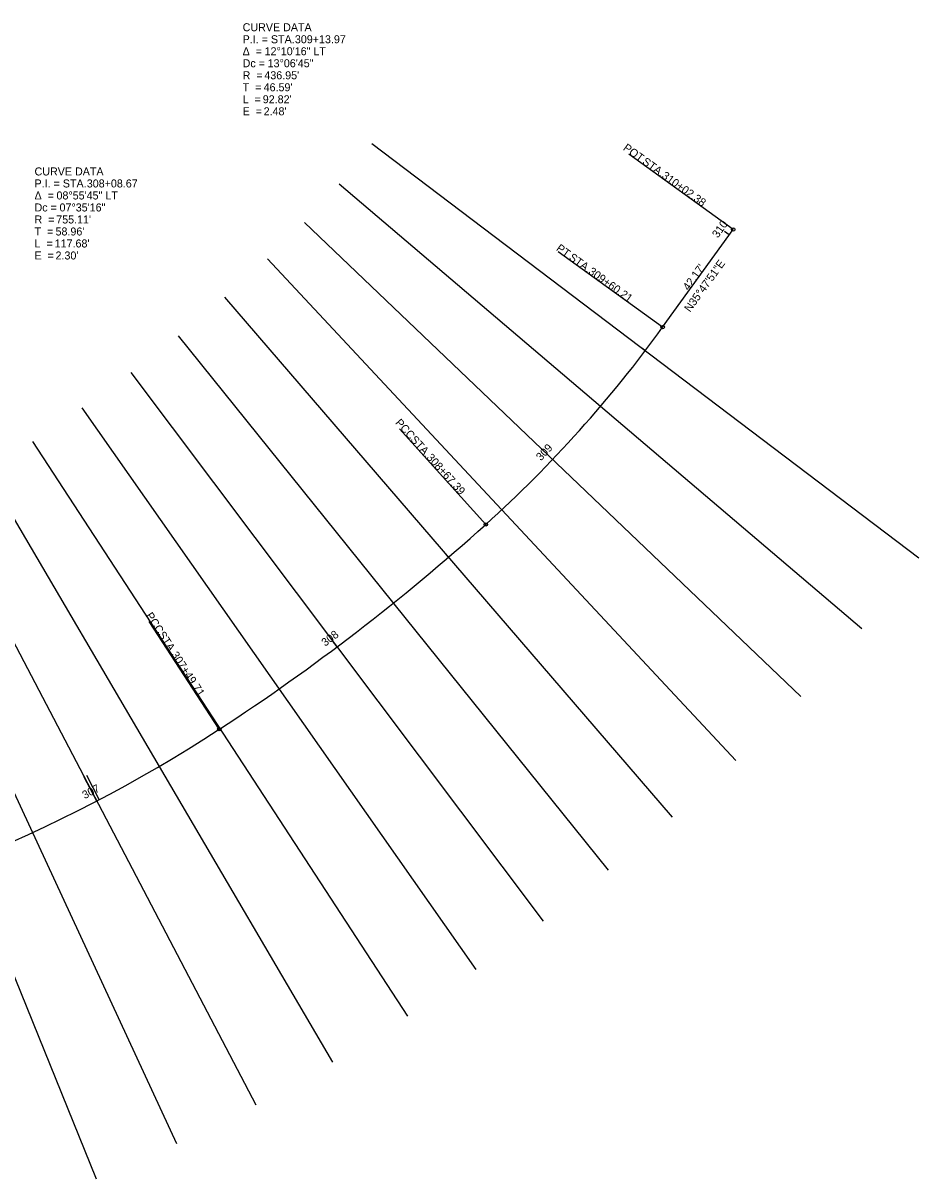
# Model space of a CAD drawing. Extents: x 153902 to 157473, y 413085 to 414252.
# Drawn here: x 154466.5 to 154779.8, y 413626.5 to 414030.9 of the extents above; entities that cross this region are included whole.
import ezdxf

# ---------------------------------------------------------------- set-up
doc = ezdxf.new("R2010")
doc.units = 0
for name, color, linetype in [('GE_P_Alignment', 7, 'Continuous'), ('GE_P_Alignment_100_Bearings', 7, 'Continuous'), ('GE_P_Alignment_100_Cardinal_Points', 7, 'Continuous'), ('GE_P_Alignment_100_Distances', 7, 'Continuous'), ('GE_P_Alignment_100_Stations', 7, 'Continuous'), ('PF_X_Ground_Line', 7, 'Continuous'), ('PM_X_Cells', 7, 'Continuous'), ('PV_X_Text', 7, 'Continuous')]:
    doc.layers.add(name, color=color, linetype=linetype)

msp = doc.modelspace()

# ---------------------------------------------------------------- linework, layer by layer
at = {"layer": 'GE_P_Alignment'}
msp.add_line((154690.16, 413924.47), (154714.83, 413958.67), dxfattribs=at)
for centre, radius, start, end in [((154335.75, 414180.05), 436.95, 312.0315, 324.2025), ((154122.74, 414416.37), 755.11, 303.10232, 312.03145), ((154251.74, 414218.49), 518.89, 280.6558, 303.1023)]:
    msp.add_arc(centre, radius, start, end, dxfattribs=at)
at = {"layer": 'GE_P_Alignment_100_Cardinal_Points'}
for p, q in [((154714.83, 413958.67), (154678.33, 413984.99)), ((154690.16, 413924.47), (154653.66, 413950.79)), ((154628.31, 413855.49), (154598.18, 413888.92)), ((154535.13, 413783.82), (154510.55, 413821.51))]:
    msp.add_line(p, q, dxfattribs=at)
for centre in [(154714.83, 413958.67), (154690.16, 413924.47), (154628.31, 413855.49), (154535.13, 413783.82)]:
    msp.add_circle(centre, 0.6, dxfattribs=at)
at = {"layer": 'PF_X_Ground_Line'}
for p, q in [((154713.43, 413956.74), (154711.81, 413957.91)), ((154684.09, 413916.26), (154683.14, 413916.98)), ((154651.69, 413878.21), (154650.25, 413879.59)), ((154615.26, 413844), (154614.48, 413844.91)), ((154576.31, 413812.67), (154575.11, 413814.27)), ((154535.37, 413783.98), (154534.71, 413784.98)), ((154492.25, 413758.71), (154491.32, 413760.48))]:
    msp.add_line(p, q, dxfattribs=at)
at = {"layer": 'PM_X_Cells'}
for p, q in [((154492.25, 413758.71), (154487.77, 413767.27)), ((154488.65, 413767.74), (154493.13, 413759.17))]:
    msp.add_line(p, q, dxfattribs=at)
at = {"layer": 'PV_X_Text'}
for p, q in [((154588.43, 413988.7), (154779.76, 413843.82)), ((154759.8, 413818.98), (154577.07, 413974.57)), ((154564.93, 413961.11), (154738.46, 413795.32)), ((154715.8, 413772.92), (154552.03, 413948.36)), ((154536.99, 413934.96), (154693.53, 413753.04)), ((154671.26, 413734.51), (154520.83, 413921.51)), ((154504.23, 413908.61), (154648.39, 413716.73)), ((154624.94, 413699.71), (154487.21, 413896.26)), ((154469.79, 413884.48), (154600.94, 413683.48)), ((154574.79, 413667.29), (154453.44, 413874.35)), ((154436.63, 413865.04), (154547.87, 413652.37)), ((154520.26, 413638.77), (154419.39, 413856.54)), ((154401.76, 413848.89), (154492.03, 413626.51))]:
    msp.add_line(p, q, dxfattribs=at)

# ---------------------------------------------------------------- texts
at = {"layer": 'GE_P_Alignment_100_Bearings'}
msp.add_text('N35°47\'51"E', height=2.8, rotation=54.2025, dxfattribs=at).set_placement((154699.74, 413929.55))
at = {"layer": 'GE_P_Alignment_100_Cardinal_Points'}
for s, rotation, p in [('POT', 324.2025, (154676.09, 413986.66)), (' STA. ', 324.2025, (154681.93, 413982.45)), ('310+02.38', 324.2025, (154689.6, 413976.92)), ('PT', 324.2025, (154652.7, 413951.53)), (' STA. ', 324.2025, (154656.28, 413948.95)), ('309+60.21', 324.2025, (154663.95, 413943.42)), ('PCC', 312.0315, (154596.46, 413890.89)), (' STA. ', 312.0315, (154601.07, 413885.77)), ('308+67.39', 312.0315, (154607.4, 413878.75)), ('PCC', 303.1023, (154509.25, 413823.59)), (' STA. ', 303.1023, (154513.01, 413817.82)), ('307+49.71', 303.1023, (154518.17, 413809.9))]:
    msp.add_text(s, height=2.8, rotation=rotation, dxfattribs=at).set_placement(p)
at = {"layer": 'GE_P_Alignment_100_Distances'}
for s, p in [('CURVE DATA', (154543.28, 414028.02)), ('P.I. = STA. ', (154543.28, 414023.82)), ('309+13.97', (154561.55, 414023.82)), ('Δ  = ', (154543.28, 414019.62)), ('12°10\'16" LT', (154550.96, 414019.62)), ('Dc = ', (154543.28, 414015.42)), ('13°06\'45"', (154552.02, 414015.42)), ('R  = ', (154543.28, 414011.22)), ("436.95'", (154550.87, 414011.22)), ('T  = ', (154543.28, 414007.02)), ("46.59'", (154550.62, 414007.02)), ('L  = ', (154543.28, 414002.82)), ("92.82'", (154550.32, 414002.82)), ('E  = ', (154543.28, 413998.62)), ("2.48'", (154550.62, 413998.62)), ('CURVE DATA', (154470.51, 413977.57)), ('P.I. = STA. ', (154470.51, 413973.37)), ('308+08.67', (154488.78, 413973.37)), ('Δ  = ', (154470.51, 413969.17)), ('08°55\'45" LT', (154478.19, 413969.17)), ('Dc = ', (154470.51, 413964.97)), ('07°35\'16"', (154479.25, 413964.97)), ('R  = ', (154470.51, 413960.77)), ("755.11'", (154478.09, 413960.77)), ('T  = ', (154470.51, 413956.57)), ("58.96'", (154477.85, 413956.57)), ('L  = ', (154470.51, 413952.37)), ("117.68'", (154477.55, 413952.37)), ('E  = ', (154470.51, 413948.17)), ("2.30'", (154477.85, 413948.17))]:
    msp.add_text(s, height=2.8, dxfattribs=at).set_placement(p)
at = {"layer": 'GE_P_Alignment_100_Stations'}
msp.add_text("42.17'", height=2.8, rotation=54.2025, dxfattribs=at).set_placement((154699.22, 413937.07))
at = {"layer": 'PF_X_Ground_Line'}
for s, rotation, p in [('310', 54.2025, (154709.45, 413955.49)), ('309', 46.3079, (154647.59, 413877.54)), ('308', 36.9183, (154572.14, 413812.66)), ('307', 27.6135, (154488.06, 413759.34))]:
    msp.add_text(s, height=2.8, rotation=rotation, dxfattribs=at).set_placement(p)

doc.saveas('drawing.dxf')
